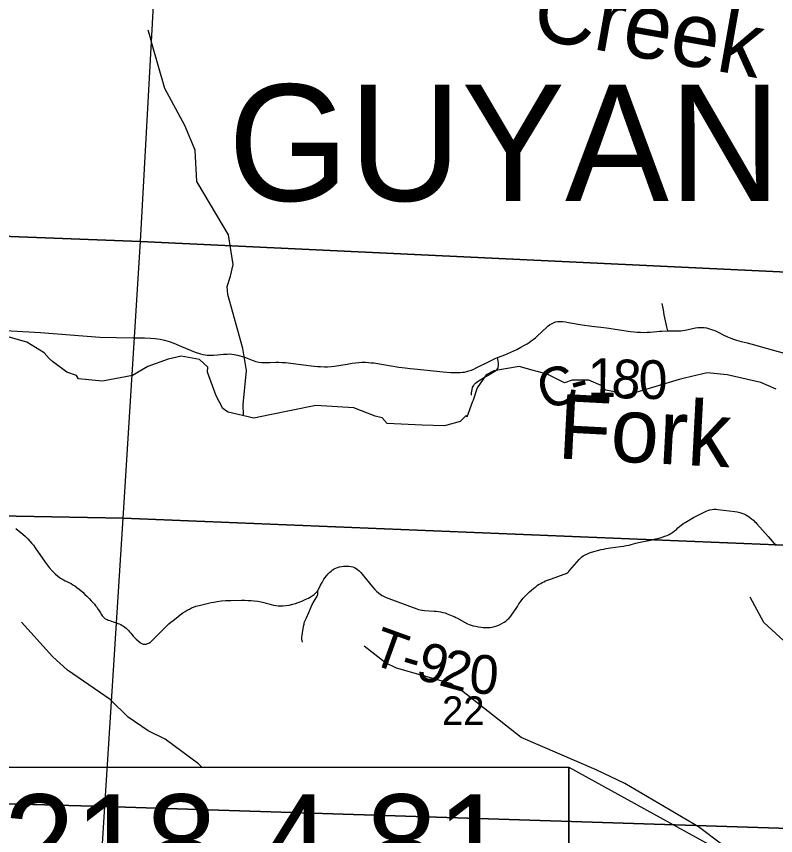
# Model space of a CAD drawing. Extents: x 0 to 34, y 0 to 22.
# Drawn here: x 2.833 to 3.946, y 16.555 to 17.756 of the extents above; entities that cross this region are included whole.
import ezdxf

# ---------------------------------------------------------------- set-up
doc = ezdxf.new("R2010")
doc.units = 0
for name, color, linetype in [('Default', 7, 'Continuous'), ('GM_X_County_Road', 7, 'Continuous'), ('GM_X_County_Road_Text', 7, 'Continuous'), ('GM_X_Minor_River', 7, 'Continuous'), ('GM_X_Minor_River_Text', 7, 'Continuous'), ('GM_X_Section', 7, 'Continuous'), ('GM_X_Section_Text', 7, 'Continuous'), ('GM_X_Township_Road', 7, 'Continuous'), ('GM_X_Township_Road_Text', 7, 'Continuous'), ('GM_X_Township_Text', 7, 'Continuous'), ('TX_P_1', 7, 'Continuous')]:
    doc.layers.add(name, color=color, linetype=linetype)

msp = doc.modelspace()

# ---------------------------------------------------------------- linework, layer by layer
at = {"layer": 'Default'}
for points in [[(2.1, 18.4931), (2.1, 17.4608), (3.0145, 17.426), (3.0707, 18.4461)], [(2.1, 17.4608), (2.1, 17.0372), (2.9891, 17.0205), (3.0145, 17.426)], [(2.1, 17.0372), (2.1, 16.6219), (2.9626, 16.5982), (2.9891, 17.0205)], [(2.1, 16.6219), (2.1, 16.4177), (2.9504, 16.4035), (2.9626, 16.5982)]]:
    msp.add_lwpolyline(points, close=True, dxfattribs=at)
at = {"layer": 'GM_X_County_Road'}
for points in [[(3.0205, 17.2846), (3.0295, 17.2842), (3.0363, 17.2838), (3.0434, 17.2828), (3.0501, 17.2813), (3.0565, 17.2794), (3.0635, 17.277), (3.0749, 17.2721), (3.095, 17.2638), (3.1027, 17.2613), (3.106, 17.2604), (3.1094, 17.2597), (3.1125, 17.2593), (3.1153, 17.2592), (3.1179, 17.2592), (3.1217, 17.2595), (3.1274, 17.2599), (3.1362, 17.2607), (3.1417, 17.2609), (3.1449, 17.261), (3.1486, 17.2607), (3.152, 17.2603), (3.1568, 17.2594), (3.1621, 17.2579), (3.1685, 17.2556), (3.1783, 17.2518), (3.1837, 17.2501), (3.188, 17.2491), (3.1924, 17.2485), (3.1974, 17.2483), (3.2043, 17.2485), (3.213, 17.2489), (3.2176, 17.249), (3.2222, 17.2487), (3.2271, 17.2483), (3.2647, 17.2437), (3.2691, 17.2432), (3.2739, 17.2428), (3.2787, 17.2426), (3.2843, 17.2424), (3.289, 17.2424), (3.2942, 17.2426), (3.2991, 17.2432), (3.3082, 17.2446), (3.3174, 17.2463), (3.3247, 17.2475), (3.3298, 17.2482), (3.3345, 17.2486), (3.3393, 17.2489), (3.3439, 17.2489), (3.3487, 17.2487), (3.3528, 17.2482), (3.3566, 17.2478), (3.371, 17.2454), (3.3933, 17.2419), (3.4028, 17.2406), (3.4097, 17.2397), (3.4159, 17.2391), (3.4583, 17.2349), (3.4694, 17.2341), (3.4768, 17.2338), (3.4798, 17.2338), (3.4832, 17.2339), (3.4867, 17.2342), (3.4898, 17.2345), (3.4928, 17.2351), (3.4961, 17.2361), (3.4997, 17.2373), (3.5034, 17.2388), (3.5069, 17.2406), (3.5268, 17.2505), (3.5317, 17.253), (3.5356, 17.2547), (3.5379, 17.2556), (3.5393, 17.2561), (3.5489, 17.2598), (3.5662, 17.2676), (3.5723, 17.2708), (3.5776, 17.2737), (3.5815, 17.2761), (3.5844, 17.278), (3.5874, 17.2802), (3.5904, 17.2823), (3.5935, 17.2848), (3.596, 17.287), (3.6102, 17.3005), (3.6123, 17.3023), (3.6143, 17.3037), (3.617, 17.3054), (3.62, 17.3068), (3.623, 17.3079), (3.6264, 17.3084), (3.6299, 17.3087), (3.6334, 17.3086), (3.6376, 17.3081), (3.6418, 17.3072), (3.662, 17.3035), (3.6761, 17.3016), (3.6893, 17.3002), (3.6937, 17.2997), (3.6979, 17.2991), (3.733, 17.294), (3.7382, 17.2935), (3.7427, 17.2931), (3.7475, 17.2928), (3.7526, 17.2927), (3.7573, 17.2928), (3.7618, 17.293), (3.7665, 17.2935), (3.7713, 17.294), (3.7756, 17.2944), (3.779, 17.2946), (3.7875, 17.2949), (3.8034, 17.2949), (3.8064, 17.2951), (3.8096, 17.2954), (3.8128, 17.2958), (3.8282, 17.2991), (3.8315, 17.2996), (3.8345, 17.2998), (3.8374, 17.2998), (3.8406, 17.2996), (3.8442, 17.2991), (3.8474, 17.2984), (3.8501, 17.2975), (3.8532, 17.2965), (3.8563, 17.2953), (3.8621, 17.2927), (3.8697, 17.2886), (3.8752, 17.286), (3.8797, 17.2841), (3.884, 17.2825), (3.8882, 17.2811), (3.8949, 17.2793), (3.9038, 17.2771), (3.9147, 17.2742), (3.923, 17.2719), (3.9319, 17.2694), (3.9755, 17.2575)], [(2.7034, 17.2806), (2.7375, 17.2889), (2.7509, 17.2917), (2.7594, 17.2934), (2.7673, 17.2947), (2.7765, 17.2958), (2.7858, 17.2964), (2.7951, 17.2965), (2.8074, 17.296), (2.8682, 17.2926), (2.9549, 17.2858), (3.004, 17.2848), (3.0205, 17.2846)]]:
    msp.add_lwpolyline(points, dxfattribs=at)
at = {"layer": 'GM_X_Minor_River'}
for points in [[(3.1658, 17.1714), (3.1654, 17.187), (3.1703, 17.2366), (3.1649, 17.269), (3.1427, 17.3483), (3.1419, 17.3598), (3.1465, 17.3748), (3.1505, 17.3921), (3.1438, 17.4356), (3.1172, 17.4798), (3.0974, 17.5138), (3.0947, 17.5595), (3.0795, 17.5956), (3.0506, 17.6501), (3.0307, 17.7179), (3.0294, 17.724), (3.0259, 17.7352)], [(3.9464, 17.2095), (3.9241, 17.219), (3.8746, 17.2306), (3.8454, 17.2332), (3.8118, 17.2255), (3.8043, 17.2236), (3.7408, 17.2048), (3.7207, 17.1991), (3.7094, 17.2055), (3.6965, 17.2081), (3.6897, 17.2146), (3.6719, 17.2225), (3.6474, 17.2224), (3.636, 17.2186), (3.6107, 17.2314), (3.5888, 17.2375), (3.5695, 17.2427), (3.5324, 17.2362), (3.5211, 17.2305), (3.5079, 17.2114), (3.5022, 17.1935), (3.5015, 17.1916), (3.4928, 17.1684), (3.4921, 17.1707), (3.4834, 17.1619), (3.4603, 17.1558), (3.4274, 17.1569), (3.3764, 17.159), (3.3688, 17.1673), (3.3586, 17.17), (3.3272, 17.1821), (3.2717, 17.1857), (3.2044, 17.1718), (3.1806, 17.1672), (3.1432, 17.1759), (3.1409, 17.1774), (3.1356, 17.1812), (3.1254, 17.1998), (3.1129, 17.2343), (3.1132, 17.2415), (3.1011, 17.2529), (3.0743, 17.2578), (3.0554, 17.2535), (3.0255, 17.2428), (3.0032, 17.2295), (2.959, 17.2214), (2.9239, 17.2247), (2.9208, 17.2293), (2.9068, 17.2342), (2.8857, 17.2501), (2.8811, 17.2546), (2.8736, 17.2626), (2.8482, 17.2785), (2.8187, 17.2868)], [(4.3191, 16.2364), (4.3286, 16.2594), (4.3296, 16.2772), (4.3221, 16.3181), (4.3114, 16.3507), (4.2973, 16.4225), (4.2824, 16.453), (4.2655, 16.4703), (4.2519, 16.4836), (4.2367, 16.5167), (4.2116, 16.538), (4.1877, 16.5733), (4.0987, 16.692), (4.0621, 16.7448), (4.0288, 16.766), (4.0171, 16.7789), (4.0136, 16.7881), (4.0099, 16.7928), (3.9283, 16.8675), (3.9083, 16.905)], [(3.1047, 16.6555), (3.0995, 16.6606), (3.0507, 16.6967), (3.0258, 16.7088), (2.9965, 16.7291), (2.9705, 16.755), (2.9079, 16.798), (2.8858, 16.8177), (2.8401, 16.8681)], [(3.8542, 16.1051), (3.8688, 16.1253), (3.8834, 16.1644), (3.886, 16.2916), (3.8881, 16.3311), (3.8932, 16.3562), (3.919, 16.4179), (3.9165, 16.457), (3.9038, 16.4956), (3.8812, 16.5266), (3.8663, 16.5429), (3.8324, 16.5681), (3.7246, 16.6317), (3.6823, 16.6516), (3.5724, 16.6992), (3.485, 16.7682), (3.469, 16.7784), (3.39, 16.8007), (3.374, 16.8086), (3.3423, 16.8328)]]:
    msp.add_lwpolyline(points, dxfattribs=at)
at = {"layer": 'GM_X_Section'}
for points in [[(3.0707, 18.4461), (4.1036, 18.4009), (4.0444, 17.3771), (3.0145, 17.426)], [(3.0145, 17.426), (4.0444, 17.3771), (4.0188, 16.9784), (2.9891, 17.0205)], [(2.9891, 17.0205), (4.0188, 16.9784), (3.9959, 16.5649), (2.9626, 16.5982)], [(2.9626, 16.5982), (3.9959, 16.5649), (3.9864, 16.3863), (2.9504, 16.4035)]]:
    msp.add_lwpolyline(points, close=True, dxfattribs=at)
at = {"layer": 'GM_X_Township_Road'}
for points in [[(3.7875, 17.2949), (3.7861, 17.3007), (3.7823, 17.3184), (3.781, 17.3259), (3.7795, 17.3348)], [(3.5, 17.2007), (3.4998, 17.203), (3.4999, 17.2042), (3.5007, 17.2091), (3.5015, 17.2121), (3.5026, 17.2143), (3.5039, 17.2164), (3.5057, 17.2183), (3.5079, 17.22), (3.5112, 17.2222), (3.5175, 17.2261), (3.5267, 17.2313), (3.5338, 17.2356), (3.5359, 17.2371), (3.5369, 17.2379), (3.538, 17.2391), (3.5387, 17.2403), (3.539, 17.2419), (3.5393, 17.2441), (3.5394, 17.2467), (3.5392, 17.2486), (3.539, 17.2506), (3.5385, 17.2528), (3.5379, 17.2556)], [(2.832, 17.0052), (2.8352, 17.003), (2.8393, 16.9997), (2.8422, 16.9972), (2.8461, 16.9934), (2.8495, 16.99), (2.8524, 16.9869), (2.8556, 16.9834), (2.8578, 16.9807), (2.8604, 16.9772), (2.8751, 16.9558), (2.8811, 16.9481), (2.8851, 16.9434), (2.8895, 16.9391), (2.8937, 16.9355), (2.8977, 16.9326), (2.902, 16.9301), (2.9043, 16.9288), (2.9067, 16.9276), (2.9097, 16.9263), (2.9129, 16.9246), (2.9158, 16.9229), (2.9185, 16.9212), (2.9216, 16.919), (2.9246, 16.9167), (2.9276, 16.9142), (2.9301, 16.9119), (2.9332, 16.9089), (2.9362, 16.906), (2.9394, 16.9028), (2.9426, 16.8995), (2.9449, 16.897), (2.9471, 16.8944), (2.9488, 16.8922), (2.9505, 16.89), (2.9526, 16.8869), (2.9544, 16.8842), (2.9559, 16.8819), (2.9571, 16.8799), (2.9585, 16.8776), (2.9601, 16.8758), (2.9619, 16.8742), (2.9631, 16.8732), (2.9643, 16.8725), (2.9659, 16.8718), (2.9674, 16.8712), (2.9696, 16.8704), (2.9747, 16.8687), (2.9798, 16.8671), (2.9817, 16.8664), (2.9837, 16.8655), (2.9857, 16.8645), (2.9877, 16.8634), (2.9896, 16.8624), (2.9916, 16.861), (2.9935, 16.8595), (2.9952, 16.8581), (2.9964, 16.8569), (2.9976, 16.8555), (2.9987, 16.854), (3.0004, 16.8518), (3.002, 16.8499), (3.0039, 16.8477), (3.0084, 16.8433), (3.0114, 16.8406), (3.014, 16.8384), (3.0157, 16.8372), (3.0176, 16.8363), (3.0187, 16.836), (3.0198, 16.8358), (3.0209, 16.8358), (3.0219, 16.8358), (3.0231, 16.836), (3.0242, 16.8362), (3.0257, 16.8368), (3.0271, 16.8375), (3.0283, 16.8382), (3.0294, 16.8389), (3.0305, 16.8398), (3.0379, 16.8472), (3.0564, 16.8656), (3.0593, 16.8681), (3.0626, 16.8708), (3.0668, 16.8741), (3.0729, 16.8788), (3.077, 16.8816), (3.0802, 16.8837), (3.0833, 16.8855), (3.0864, 16.8874), (3.0896, 16.8889), (3.0926, 16.8903), (3.096, 16.8915), (3.1005, 16.8927), (3.1182, 16.8967), (3.1224, 16.8975), (3.127, 16.8983), (3.1335, 16.8992), (3.1397, 16.8997), (3.1472, 16.9), (3.1629, 16.9004), (3.1678, 16.9003), (3.1721, 16.9001), (3.1767, 16.8999), (3.1815, 16.8994), (3.1866, 16.8988), (3.1916, 16.898), (3.1955, 16.8971), (3.1991, 16.8961), (3.2026, 16.8951), (3.2063, 16.894), (3.2098, 16.8931), (3.213, 16.8924), (3.2167, 16.892), (3.22, 16.892), (3.2234, 16.8922), (3.228, 16.8926), (3.2324, 16.8932), (3.238, 16.8944), (3.2421, 16.8957), (3.246, 16.8969), (3.251, 16.8989), (3.256, 16.9011), (3.2608, 16.9034), (3.2636, 16.905), (3.2664, 16.9068), (3.2691, 16.9089), (3.2713, 16.9108), (3.2746, 16.914), (3.2787, 16.9221), (3.2809, 16.9264), (3.2835, 16.9309), (3.2854, 16.9337), (3.2873, 16.9362), (3.2898, 16.939), (3.292, 16.9412), (3.2941, 16.943), (3.2963, 16.9446), (3.2987, 16.9461), (3.3011, 16.9473), (3.3035, 16.9483), (3.3062, 16.9492), (3.3092, 16.9499), (3.3122, 16.9502), (3.3149, 16.9503), (3.3174, 16.9502), (3.3199, 16.95), (3.323, 16.9496), (3.3257, 16.949), (3.3283, 16.9481), (3.3308, 16.9468), (3.333, 16.9452), (3.3353, 16.9432), (3.3374, 16.9409), (3.3394, 16.9385), (3.3414, 16.9361), (3.3549, 16.9197), (3.3582, 16.9162), (3.361, 16.9133), (3.3636, 16.9109), (3.3664, 16.9088), (3.3688, 16.9073), (3.3711, 16.9061), (3.3747, 16.9045), (3.4051, 16.8928), (3.4195, 16.8878), (3.4221, 16.8869), (3.4248, 16.8862), (3.4275, 16.8857), (3.431, 16.8854), (3.4453, 16.8844), (3.4481, 16.8841), (3.4514, 16.8837), (3.4546, 16.8832), (3.4579, 16.8825), (3.4611, 16.8816), (3.4644, 16.8805), (3.4717, 16.8775), (3.4743, 16.8764), (3.4768, 16.8751), (3.4792, 16.8738), (3.4918, 16.8668), (3.4939, 16.8656), (3.4966, 16.8645), (3.4992, 16.8636), (3.5023, 16.8628), (3.506, 16.8621), (3.5103, 16.8613), (3.5138, 16.8608), (3.5168, 16.8605), (3.5201, 16.8603), (3.5233, 16.8603), (3.527, 16.8605), (3.5301, 16.8609), (3.5336, 16.8617), (3.537, 16.8628), (3.5409, 16.8643), (3.5443, 16.866), (3.5477, 16.868), (3.5501, 16.8698), (3.5527, 16.8719), (3.555, 16.8742), (3.5574, 16.877), (3.5595, 16.8798), (3.5611, 16.8819), (3.5671, 16.8913), (3.5694, 16.8949), (3.5715, 16.8979), (3.5737, 16.9007), (3.5757, 16.9032), (3.5776, 16.9054), (3.5798, 16.9078), (3.5824, 16.9103), (3.5846, 16.9125), (3.5876, 16.9151), (3.5912, 16.918), (3.5939, 16.92), (3.5966, 16.9221), (3.5989, 16.9236), (3.6013, 16.925), (3.6034, 16.9261), (3.6057, 16.9272), (3.6084, 16.9285), (3.611, 16.9295), (3.6139, 16.9306), (3.617, 16.9317), (3.6357, 16.9383), (3.6378, 16.9391), (3.6394, 16.9399), (3.6411, 16.9411), (3.6426, 16.9425), (3.6441, 16.9441), (3.6578, 16.96), (3.6595, 16.9618), (3.6615, 16.9636), (3.6636, 16.9652), (3.6664, 16.9669), (3.6696, 16.9683), (3.6728, 16.9695), (3.6759, 16.9705), (3.6898, 16.9744), (3.6937, 16.9753), (3.6971, 16.976), (3.7, 16.9765), (3.7033, 16.977), (3.7181, 16.9789), (3.7224, 16.9795), (3.7263, 16.9802), (3.7307, 16.981), (3.734, 16.9818), (3.7373, 16.9828), (3.7408, 16.9837), (3.7448, 16.9847), (3.7644, 16.9887), (3.7701, 16.99), (3.7751, 16.9913), (3.7792, 16.9926), (3.7832, 16.994), (3.7865, 16.9953), (3.7895, 16.9967), (3.7921, 16.9981), (3.7947, 16.9999), (3.7974, 17.0019), (3.8001, 17.0041), (3.8024, 17.0062), (3.8048, 17.0082), (3.8069, 17.0101), (3.8089, 17.0116), (3.811, 17.013), (3.8131, 17.0143), (3.8254, 17.0215), (3.8407, 17.0293), (3.8436, 17.0307), (3.8463, 17.0318), (3.8493, 17.0328), (3.8523, 17.0334), (3.8551, 17.0338), (3.8579, 17.0337), (3.8606, 17.0334), (3.8857, 17.0302), (3.8892, 17.0296), (3.8929, 17.0289), (3.8961, 17.028), (3.899, 17.0269), (3.902, 17.0254), (3.9045, 17.0239), (3.907, 17.0222), (3.9103, 17.0196), (3.9129, 17.0175), (3.9148, 17.0158), (3.9166, 17.014), (3.9182, 17.0123), (3.9344, 16.9934), (3.9459, 16.9804)], [(3.252, 16.8387), (3.2512, 16.8431), (3.2512, 16.8449), (3.2513, 16.8467), (3.2516, 16.8485), (3.2528, 16.856), (3.2541, 16.8637), (3.2544, 16.8654), (3.2548, 16.8669), (3.2553, 16.8685), (3.2558, 16.8697), (3.2579, 16.8746), (3.2612, 16.8821), (3.2664, 16.894), (3.2672, 16.8956), (3.268, 16.897), (3.2693, 16.899), (3.2706, 16.9011), (3.2731, 16.9053), (3.2737, 16.9063), (3.2742, 16.9075), (3.2745, 16.9086), (3.2746, 16.9095), (3.2747, 16.9104), (3.2747, 16.9118), (3.2746, 16.914)]]:
    msp.add_lwpolyline(points, dxfattribs=at)
at = {"layer": 'TX_P_1'}
for points in [[(2.3381, 16.6555), (3.6423, 16.6555), (3.6423, 16.4348), (2.3381, 16.4348)], [(3.6423, 16.6555), (4.3349, 16.2743), (3.6423, 16.4348)]]:
    msp.add_lwpolyline(points, close=True, dxfattribs=at)

# ---------------------------------------------------------------- texts
at = {"layer": 'GM_X_County_Road_Text'}
for s, rotation, p in [('1', 359.5811, (3.6697, 17.1982)), ('8', 354.6607, (3.7034, 17.198)), ('0', 1.4818, (3.7456, 17.1945)), ('C', 18.9515, (3.608, 17.1778)), ('-', 14.9583, (3.6511, 17.1927))]:
    msp.add_text(s, height=0.0568, rotation=rotation, dxfattribs=at).set_placement(p)
at = {"layer": 'GM_X_Minor_River_Text'}
for s, rotation, p in [('Creek', 350.0126, (3.5857, 17.7237)), ('Fork', 357.013, (3.6249, 17.1081))]:
    msp.add_text(s, height=0.09469, rotation=rotation, dxfattribs=at).set_placement(p)
at = {"layer": 'GM_X_Section_Text'}
msp.add_text('22', height=0.04186, rotation=0, dxfattribs=at).set_placement((3.4566, 16.7176))
at = {"layer": 'GM_X_Township_Road_Text'}
for s, rotation, p in [('T', 340.1352, (3.3495, 16.8086)), ('9', 343.8492, (3.4157, 16.7863)), ('2', 344.5951, (3.4501, 16.7764)), ('-', 343.5921, (3.3931, 16.793)), ('0', 354.9875, (3.4949, 16.7651))]:
    msp.add_text(s, height=0.0568, rotation=rotation, dxfattribs=at).set_placement(p)
at = {"layer": 'GM_X_Township_Text'}
msp.add_text('GUYAN', height=0.17045, rotation=0, dxfattribs=at).set_placement((3.1431, 17.4853))
at = {"layer": 'TX_P_1'}
msp.add_text('GAL-218-4.81', height=0.14, dxfattribs=at).set_placement((2.3774, 16.4758))

doc.saveas('drawing.dxf')
